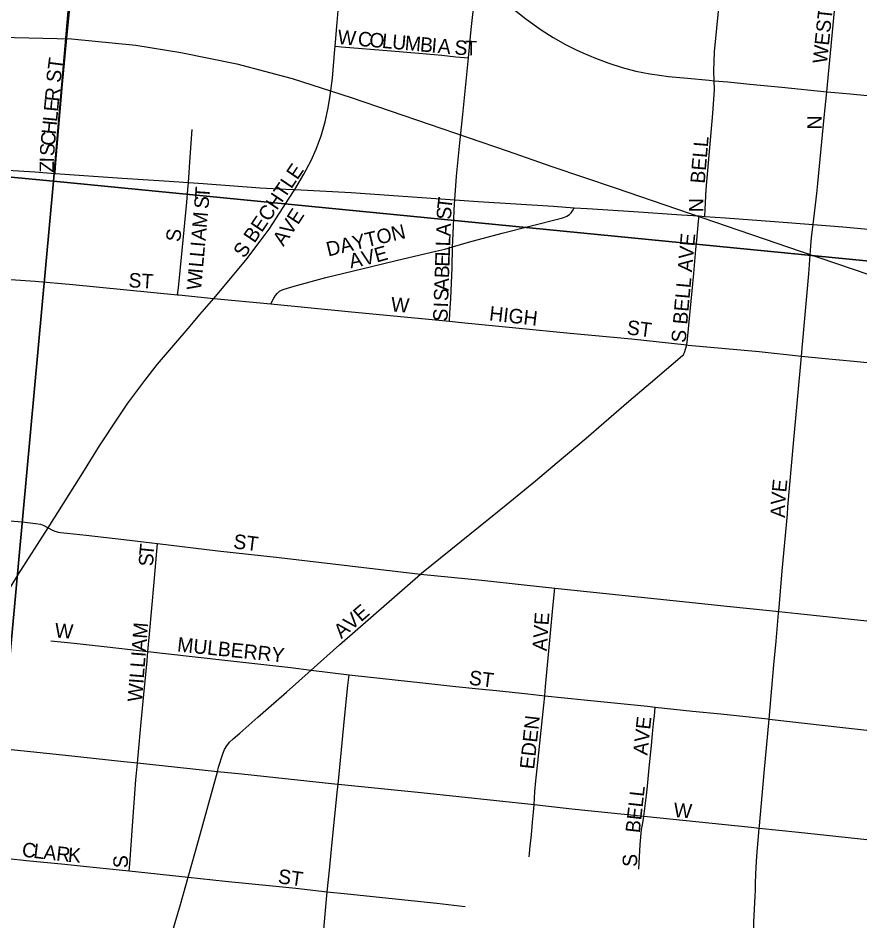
# Model space of a CAD drawing. Extents: x 1410790 to 1770854, y 566777 to 831614.
# Drawn here: x 1593463 to 1596372, y 701692 to 704811 of the extents above; entities that cross this region are included whole.
import ezdxf

# ---------------------------------------------------------------- set-up
doc = ezdxf.new("R2010")
doc.units = 0
for name, color, linetype in [('GM_X_City_Street', 7, 'Continuous'), ('GM_X_City_Street_Text', 7, 'Continuous'), ('GM_X_Rail_Line', 7, 'Continuous'), ('GM_X_Section', 7, 'Continuous'), ('GM_X_US_Route', 7, 'Continuous')]:
    doc.layers.add(name, color=color, linetype=linetype)

msp = doc.modelspace()

# ---------------------------------------------------------------- linework, layer by layer
at = {"layer": 'GM_X_City_Street'}
for points in [[(1593591.5, 704274.8), (1593592.7, 704294.8), (1593595.5, 704338.7), (1593616.8, 704582.3), (1593630.3, 704729.5), (1593642.2, 704845), (1593672.7, 705171), (1593676.9, 705216)], [(1595868.6, 704595.1), (1595867.1, 704629.6), (1595869.9, 704695.3), (1595894.2, 704941.3), (1595903.9, 705053.4)], [(1596257.6, 704556.7), (1596296.9, 704970.9), (1596301.7, 705017)], [(1595019, 704673.5), (1595029.1, 704772.2), (1595046.8, 704939.3)], [(1594558.9, 704714.2), (1594565.2, 704795.6), (1594570.3, 704851.1)], [(1594419.3, 704219.3), (1594450.8, 704272.4), (1594475.4, 704318.9), (1594493.3, 704358.2), (1594510.7, 704404.3), (1594524.6, 704453), (1594534.8, 704501.3), (1594541.5, 704544.2), (1594549.1, 704603.7), (1594558.1, 704704.2), (1594558.9, 704714.2)], [(1594558.9, 704714.2), (1594580.9, 704712.4), (1594751.7, 704698.4), (1594848.3, 704690.5), (1594927.6, 704682.9), (1594975.8, 704677.4), (1595005.3, 704674.7), (1595019, 704673.5)], [(1594971.8, 704183.9), (1594977.8, 704265.5), (1594989.4, 704379.9), (1595000.3, 704477.8), (1595019, 704673.5)], [(1595835.8, 704126.4), (1595837.1, 704151.4), (1595840.7, 704218.9), (1595864, 704481.7), (1595869, 704563.8), (1595868.6, 704595.1)], [(1596210.6, 704098.2), (1596215.1, 704137.7), (1596218.4, 704166.4), (1596222.8, 704205.3), (1596226.7, 704239.4), (1596249, 704468), (1596257.6, 704556.7)], [(1594051.7, 704243.7), (1594057.2, 704331), (1594064.5, 704426.5)], [(1593193.7, 704301.3), (1593262.8, 704297), (1593388.8, 704288.1), (1593521, 704279.7), (1593591.5, 704274.8)], [(1593591.5, 704274.8), (1593822.4, 704258.6), (1593967.5, 704249.5), (1594051.7, 704243.7)], [(1594014.3, 703855.3), (1594016.8, 703878.9), (1594030.5, 704008.4), (1594046.4, 704175.9), (1594049.8, 704219.1), (1594051.7, 704243.7)], [(1594051.7, 704243.7), (1594102.4, 704240.2), (1594300.1, 704225.3), (1594388, 704220.8), (1594419.3, 704219.3)], [(1594139.3, 703842.9), (1594250.4, 703975.1), (1594299.3, 704040.9), (1594330.1, 704082.3), (1594379.3, 704156.9), (1594397.5, 704185.7), (1594419.3, 704219.3)], [(1594419.3, 704219.3), (1594614, 704208.6), (1594971.8, 704183.9)], [(1594964.6, 704021.4), (1594965.5, 704042.4), (1594971.2, 704170.9), (1594971.8, 704183.9)], [(1594971.8, 704183.9), (1595053.1, 704178.3), (1595313.1, 704161.1), (1595384.3, 704156)], [(1594964.6, 704021.4), (1595019, 704037.8), (1595136.1, 704068.5), (1595336.7, 704119.2), (1595348.4, 704122.8), (1595359.6, 704127.3), (1595368.6, 704133.3), (1595373.9, 704138.5), (1595379.1, 704145.3), (1595384.3, 704156)], [(1595384.3, 704156), (1595429.4, 704153.2), (1595590.5, 704143), (1595755.5, 704131.8), (1595816.1, 704127.7)], [(1595774.1, 703682.2), (1595776, 703701.7), (1595797.7, 703928.9), (1595805.3, 704011.8), (1595808.3, 704044.2), (1595814.5, 704110.2), (1595816.1, 704127.7)], [(1595816.1, 704127.7), (1595835.8, 704126.4)], [(1595835.8, 704126.4), (1595907.1, 704121.6), (1596077.4, 704109), (1596210.6, 704098.2)], [(1596170.1, 703643.6), (1596173.7, 703683.2), (1596195.8, 703927.3), (1596202.8, 704024.1), (1596205.2, 704053.5), (1596210.6, 704098.2)], [(1596210.6, 704098.2), (1596312.7, 704090), (1596425, 704079.5), (1596630.9, 704062)], [(1594336.6, 703823.7), (1594347, 703843.2), (1594352, 703852.7), (1594359.2, 703861.4), (1594366.2, 703867.5), (1594373.3, 703871.9), (1594381.9, 703874.9), (1594416.9, 703884.8), (1594527, 703915.1), (1594683.7, 703953.4), (1594769.1, 703973.6), (1594832.6, 703988.7), (1594907, 704006.3), (1594937.1, 704013.4), (1594964.6, 704021.4)], [(1594954, 703764.1), (1594955.5, 703791.7), (1594958.2, 703842.7), (1594962.8, 703949), (1594964.6, 704021.4)], [(1593163.1, 703926.4), (1593521.7, 703902.9), (1593652.2, 703891.5), (1594014.3, 703855.3)], [(1594014.3, 703855.3), (1594018.5, 703854.9), (1594139.3, 703842.9)], [(1594091.4, 703786.9), (1594139.3, 703842.9)], [(1594139.3, 703842.9), (1594336.6, 703823.7)], [(1594336.6, 703823.7), (1594603.3, 703797.6), (1594954, 703764.1)], [(1594057.3, 703746.8), (1594091.4, 703786.9)], [(1593566.9, 703050.7), (1593692.5, 703249.1), (1593744.6, 703333.3), (1593807.9, 703429.7), (1593842.6, 703480.9), (1593900.8, 703559), (1593945.1, 703615.4), (1594057.3, 703746.8)], [(1594954, 703764.1), (1594994.8, 703760.2), (1595370.3, 703722.3), (1595582.8, 703702.7), (1595774.1, 703682.2)], [(1594853.7, 702890.8), (1594857.4, 702893.6), (1595059.7, 703057.5), (1595149.5, 703130.3), (1595250.7, 703212.2), (1595325.9, 703275.6), (1595425.9, 703359.9), (1595486.7, 703413.5), (1595573.9, 703487.4), (1595648.6, 703551.2), (1595759.3, 703645.7), (1595762, 703648.5), (1595764, 703651.2), (1595766.3, 703656.5), (1595774.1, 703682.2)], [(1595774.1, 703682.2), (1595778.5, 703681.6), (1596023.7, 703659.2), (1596170.1, 703643.6)], [(1596091.3, 702761.4), (1596103.3, 702902.3), (1596121.3, 703097.6), (1596123.5, 703123), (1596142.5, 703341.7), (1596170.1, 703643.6)], [(1596170.1, 703643.6), (1596252.4, 703635.1), (1596350.8, 703625.8), (1596433.1, 703618), (1596508.7, 703610.9), (1596594.2, 703602.8)], [(1593091.7, 703108.2), (1593165.6, 703102), (1593328.1, 703085.2), (1593409.5, 703077.1), (1593476.7, 703071), (1593522.9, 703065.7), (1593540.2, 703063), (1593546.5, 703061.2), (1593551.8, 703058.6), (1593566.9, 703050.7)], [(1593335.3, 702688.6), (1593401.7, 702788.2), (1593462.5, 702886.3), (1593566.9, 703050.7)], [(1593566.9, 703050.7), (1593582, 703042.7), (1593589.4, 703039.1), (1593594.3, 703037.5), (1593601.5, 703035.3), (1593609.6, 703033.8), (1593632.9, 703031.4), (1593698.1, 703024.6), (1593827.9, 703009.8), (1593925.7, 702998.9), (1593944.2, 702996.4)], [(1593911.5, 702623.4), (1593916.9, 702682.7), (1593933.1, 702862.8), (1593941.9, 702970), (1593944.2, 702996.4)], [(1593944.2, 702996.4), (1594153.4, 702971.2), (1594365.2, 702947.4), (1594853.7, 702890.8)], [(1594476.3, 702559), (1594574.1, 702645.7), (1594853.7, 702890.8)], [(1594853.7, 702890.8), (1595065.5, 702869.9), (1595212.1, 702853.7), (1595317.3, 702842.4)], [(1595282.8, 702470.1), (1595285.9, 702502.5), (1595304.1, 702698.9), (1595309.8, 702761), (1595315.3, 702820.2), (1595317.3, 702842.4)], [(1595317.3, 702842.4), (1595782.2, 702793.8), (1595912.5, 702779.7), (1596059.3, 702764.8), (1596091.3, 702761.4)], [(1596058.2, 702389.5), (1596074.9, 702577.5), (1596082.2, 702658.4), (1596090.8, 702755.8), (1596091.3, 702761.4)], [(1596091.3, 702761.4), (1596157, 702754.2), (1596580.2, 702709), (1596676.7, 702699.1), (1596841.8, 702681.4), (1596924.6, 702672.4)], [(1593576.6, 702659.7), (1593657, 702651.6), (1593770.9, 702638.8), (1593911.5, 702623.4)], [(1593875.3, 702237), (1593877.6, 702263.5), (1593888.6, 702379.4), (1593897.6, 702474.2), (1593908.6, 702590.9), (1593911.5, 702623.4)], [(1593911.5, 702623.4), (1593982.6, 702615.4), (1594177.9, 702593.6), (1594405.9, 702568), (1594476.3, 702559)], [(1594151.9, 702207.8), (1594155.9, 702223), (1594170.5, 702269.5), (1594176.7, 702284.2), (1594184.4, 702297.7), (1594194, 702310), (1594206, 702320.9), (1594229.7, 702340.8), (1594292, 702396), (1594328.4, 702428.2), (1594390.2, 702482.8), (1594476.3, 702559)], [(1594476.3, 702559), (1594606.9, 702542.3)], [(1594568.6, 702163.5), (1594591.3, 702391.2), (1594603, 702505.5), (1594606.9, 702542.3)], [(1594606.9, 702542.3), (1594617.3, 702541.1), (1594862.1, 702515.4), (1594975.6, 702502.3), (1595055.5, 702494.5), (1595116.6, 702488.2), (1595224.7, 702476.3), (1595282.8, 702470.1)], [(1595246.7, 702092.8), (1595249, 702138.9), (1595252.6, 702176.6), (1595259.3, 702239.7), (1595266.4, 702306.8), (1595279.7, 702437.2), (1595282.8, 702470.1)], [(1595282.8, 702470.1), (1595419.7, 702455.9), (1595638.2, 702434.3), (1595664.9, 702431.3)], [(1595625, 702053.2), (1595634.1, 702126.5), (1595637.7, 702158), (1595643.9, 702220.9), (1595651.6, 702298.9), (1595655.6, 702338.4), (1595660.1, 702384.2), (1595661.7, 702400.7), (1595664.9, 702431.3)], [(1595664.9, 702431.3), (1595793.4, 702417.1), (1595891, 702407.4), (1596053.8, 702390), (1596058.2, 702389.5)], [(1596024.4, 702011.8), (1596025.2, 702020.8), (1596041.6, 702203.4), (1596058.2, 702389.5)], [(1596058.2, 702389.5), (1596313.4, 702360.4), (1596540.8, 702334.8), (1596654.5, 702323.4), (1596752, 702313.5), (1596888.6, 702297.7)], [(1593875.3, 702237), (1593828.2, 702241.6), (1593616.3, 702264.8), (1593394.6, 702288)], [(1593847, 701864.8), (1593848.8, 701888.1), (1593852.4, 701937.6), (1593859.7, 702036.7), (1593870.2, 702179.3), (1593875.3, 702237)], [(1594151.9, 702207.8), (1593875.3, 702237)], [(1594050.7, 701843.3), (1594086.1, 701970.4), (1594151.9, 702207.8)], [(1594568.6, 702163.5), (1594545.5, 702166), (1594235.8, 702199.1), (1594151.9, 702207.8)], [(1594531.4, 701793), (1594538.8, 701868.2), (1594548.5, 701964.1), (1594566.9, 702145.9), (1594568.6, 702163.5)], [(1595246.7, 702092.8), (1594855.4, 702134.3), (1594568.6, 702163.5)], [(1595229.6, 701914.1), (1595230.6, 701925.5), (1595233.1, 701951.5), (1595235.7, 701978), (1595238.1, 702003.2), (1595241, 702033.6), (1595244.3, 702067.9), (1595246.7, 702092.8)], [(1595625, 702053.2), (1595376.9, 702078.9), (1595246.7, 702092.8)], [(1595608.5, 701870.9), (1595612.3, 701956.6), (1595617.8, 702007.6), (1595620.4, 702024.3), (1595625, 702053.2)], [(1596024.4, 702011.8), (1595996.5, 702014.7), (1595625, 702053.2)], [(1596019.8, 701621.3), (1596011.3, 701641.8), (1596008.8, 701651.4), (1596007.1, 701661.3), (1596005.9, 701673), (1596005.9, 701687.5), (1596010, 701778), (1596010.7, 701798.4), (1596011.5, 701820.8), (1596012.7, 701854.4), (1596013.4, 701875.6), (1596014.2, 701897.6), (1596016.9, 701930.5), (1596024.4, 702011.8)], [(1596854.8, 701923.5), (1596826.8, 701926.5), (1596664.3, 701943.8), (1596159.6, 701997.5), (1596024.4, 702011.8)], [(1593364.1, 701914.5), (1593491.6, 701901.6), (1593624.4, 701887.9), (1593688.7, 701881.2), (1593824.2, 701867.2), (1593847, 701864.8)], [(1593847, 701864.8), (1594050.7, 701843.3)], [(1593953.9, 701405.5), (1593971.4, 701527.7), (1593978.8, 701579.4), (1593982.2, 701600.6), (1593987.1, 701622.4), (1593996.4, 701655.3), (1594024.5, 701749.4), (1594050.7, 701843.3)], [(1594050.7, 701843.3), (1594179, 701829.8), (1594341.8, 701813.5), (1594423, 701805.1), (1594531.4, 701793)], [(1594493, 701357.4), (1594503.3, 701476.9), (1594521.6, 701689.5), (1594527.7, 701754.6), (1594531.4, 701793)], [(1594531.4, 701793), (1594601.5, 701785.4), (1594910.4, 701753.1), (1595007.8, 701741.9)]]:
    msp.add_lwpolyline(points, dxfattribs=at)
at = {"layer": 'GM_X_Rail_Line'}
msp.add_lwpolyline([(1593399.6, 704745.6), (1593647.1, 704740.2), (1593870.3, 704717.3), (1594025.7, 704692.7), (1594219.3, 704653), (1594410.5, 704602.1), (1594614, 704537.4), (1595153.1, 704352.4), (1595307.7, 704298.8), (1595526.5, 704225.2), (1596169.6, 704004.7), (1597229.5, 703644.6)], dxfattribs=at)
at = {"layer": 'GM_X_Section'}
for points in [[(1588736.5, 710042.5), (1594039.9, 709527.8), (1593585.4, 704247.5), (1588248, 704750.8)], [(1594039.9, 709527.8), (1599376.7, 708982.6), (1598860.7, 703731.2), (1593585.4, 704247.5)], [(1588248, 704750.8), (1593585.4, 704247.5), (1593108.3, 699057.6), (1587775.4, 699456.9)], [(1593585.4, 704247.5), (1598860.7, 703731.2), (1598351.3, 698519.7), (1593108.3, 699057.6)]]:
    msp.add_lwpolyline(points, close=True, dxfattribs=at)
at = {"layer": 'GM_X_US_Route'}
for points in [[(1594596.4, 705124.8), (1594678.6, 705108.4), (1594727.2, 705096.4), (1594774.9, 705081.7), (1594824.7, 705063.2), (1594886, 705037.3), (1594938, 705010), (1594969.2, 704991.7), (1595004.8, 704969.2), (1595046.8, 704939.3), (1595071.4, 704921.6), (1595139.9, 704869.8), (1595217.8, 704809.3), (1595270.9, 704771.1), (1595312, 704744.7), (1595354.6, 704720), (1595391.1, 704701.8), (1595414.5, 704691.4), (1595458.3, 704672.6), (1595504, 704655.3), (1595550.5, 704640.5), (1595597.9, 704628.3), (1595645.8, 704619), (1595679.8, 704614.3)], [(1595679.8, 704614.3), (1595710.6, 704610.1), (1595776, 704603.6), (1595851.1, 704596.6), (1595868.6, 704595.1), (1595915.4, 704590.6), (1595991.8, 704583.5), (1596102.7, 704573.1), (1596257.6, 704556.7)], [(1596257.6, 704556.7), (1596285.2, 704554.2), (1596338.1, 704549.5), (1596444.8, 704539.8), (1596602.9, 704525.5), (1596673.8, 704519), (1596763.9, 704510.9), (1597086, 704480), (1597090.5, 704479.5), (1597335.8, 704458.2), (1597563.5, 704436.9), (1597597.3, 704433.8), (1597801.8, 704414.4), (1597891.3, 704405.8), (1598038.8, 704392.3), (1598266.8, 704371.3), (1598279.7, 704370.1), (1598516.6, 704347.3)]]:
    msp.add_lwpolyline(points, dxfattribs=at)

# ---------------------------------------------------------------- texts
at = {"layer": 'GM_X_City_Street_Text'}
for s, rotation, p in [('WESTERN', 83.946, (1596258, 704652.1)), ('W', 354.8649, (1594565.4, 704722.1)), ('C', 354.8693, (1594635.5, 704715.8)), ('O', 354.8798, (1594675, 704712.3)), ('L', 354.8575, (1594718.8, 704708.4)), ('U', 354.8798, (1594753.9, 704705.2)), ('M', 354.8755, (1594797.7, 704701.3)), ('B', 354.8693, (1594850.3, 704696.6)), ('I', 354.8712, (1594889.8, 704693)), ('A', 354.8788, (1594911.7, 704691.1)), ('S', 355.7595, (1594969.5, 704685.9)), ('T', 359.216, (1595007.9, 704683.1)), ('ST', 82.8649, (1593609.2, 704586.3)), ('R', 84.5021, (1593604.7, 704521.5)), ('E', 84.5286, (1593601.3, 704486.4)), ('L', 84.5167, (1593597.9, 704451.4)), ('H', 84.5047, (1593593.7, 704407.6)), ('N', 90, (1596240.4, 704426.7)), ('C', 84.6011, (1593590, 704368.2)), ('BELL', 85.0974, (1595835.6, 704238.3)), ('S', 86.1441, (1593587.6, 704333.4)), ('Z', 89.8634, (1593587.1, 704277.1)), ('I', 88.8193, (1593587.2, 704312.1)), ('S BECHTLE', 55.9014, (1594244.4, 703979)), ('T', 86.0498, (1594123.5, 704186.6)), ('S', 85.0764, (1594120.4, 704150.6)), ('T', 83.4848, (1594960.6, 704148.6)), ('N', 90, (1595831.1, 704140.7)), ('E', 56.9855, (1594430, 704094.7)), ('S', 87.9581, (1594959.4, 704114.4)), ('M', 84.8755, (1594114.5, 704084.6)), ('V', 56.7124, (1594405.7, 704057.7)), ('S', 82.8783, (1594022.8, 704036.3)), ('A', 84.857, (1594110.6, 704040.8)), ('DAYTON', 13.3481, (1594534.6, 703987.5)), ('A', 87.9436, (1594957.3, 704057.2)), ('A', 55.1583, (1594379.7, 704020.4)), ('L', 87.9442, (1594956.1, 704022)), ('S BELL AVE', 84.8718, (1595769.6, 703688.4)), ('L', 84.8575, (1594105.5, 703983.8)), ('I', 84.8712, (1594108.6, 704018.9)), ('E', 15.5361, (1594701.8, 703966.6)), ('L', 87.9507, (1594954.8, 703986.9)), ('A', 11.5757, (1594612.3, 703946.6)), ('V', 13.5481, (1594657.2, 703955.8)), ('E', 87.9581, (1594953.5, 703951.7)), ('L', 84.8706, (1594102.3, 703948.8)), ('ST', 356.4254, (1593843.5, 703881.7)), ('W', 84.8649, (1594095.2, 703869.9)), ('I', 84.8712, (1594100.4, 703926.9)), ('B', 87.9355, (1594952.1, 703912.1)), ('A', 87.9549, (1594950.5, 703868.1)), ('S', 87.9234, (1594949.3, 703832.9)), ('W', 355.6039, (1594750, 703798.1)), ('S', 87.9507, (1594946.7, 703762.6)), ('I', 87.9452, (1594948.5, 703810.9)), ('HIGH', 353.5154, (1595089.2, 703767.3)), ('ST', 352.8783, (1595564.5, 703718.9)), ('E', 84.3071, (1596117.4, 703171.3)), ('V', 85.0321, (1596113.6, 703127.6)), ('A', 88.7979, (1596112.7, 703084.5)), ('ST', 352.8783, (1594204.9, 702979.7)), ('T', 84.2527, (1593930.8, 702951.4)), ('S', 89.0711, (1593930.3, 702917.3)), ('AVE', 40.8146, (1594580.4, 702665.1)), ('AVE', 86.0494, (1595289.9, 702623.4)), ('W', 355.6039, (1593588.4, 702671.7)), ('WILLIAM', 85.3943, (1593890.8, 702447.4)), ('MULBERRY', 354.0689, (1594011.1, 702623.3)), ('ST', 352.8733, (1595018.9, 702508.9)), ('EDEN', 83.8274, (1595246, 702214.6)), ('AVE', 83.8893, (1595637.6, 702263.2)), ('BELL', 83.6532, (1595611.2, 701994.3)), ('W', 355.5955, (1595726.8, 702051.3)), ('C', 353.3058, (1593474.4, 701914.9)), ('L', 353.3188, (1593513.8, 701910.3)), ('A', 353.3087, (1593548.7, 701906.2)), ('R', 353.9856, (1593593.1, 701901)), ('K', 355.3928, (1593633.8, 701896.7)), ('S', 90, (1593842.3, 701874.7)), ('S', 90, (1595602.3, 701879.1)), ('ST', 352.402, (1594359, 701822.5))]:
    msp.add_text(s, height=50, rotation=rotation, dxfattribs=at).set_placement(p)

doc.saveas('drawing.dxf')
